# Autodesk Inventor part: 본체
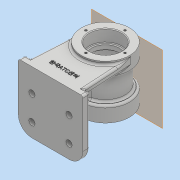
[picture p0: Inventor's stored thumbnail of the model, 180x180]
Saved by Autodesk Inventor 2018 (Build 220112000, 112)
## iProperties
Created: 2024-02
Part Number: 본체
Material: 일반
Document SubType Name: Modeling
Designer: home
Density: 1 g/cm^3
Appearance: 기본값
Author: home
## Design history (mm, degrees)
sketch "스케치2"
  geometry: L1 (-47, 45)-(47, 45); L2 (47, 45)-(47, -25); L3 (27, -45)-(-27, -45); L4 (-47, -25)-(-47, 45); L5 (-47, 45)-(47, -45); L6 (47, 45)-(-47, -45); A1 r 20 centre (27, -25) between (27, -45) and (47, -25); A2 r 20 centre (-27, -25) between (-47, -25) and (-27, -45); 1 further point
  constraints: 12 end point, 4 point on circle, 4 point on line, 4 tangent, 2 centre point, 2 midpoint, 2 parallel, 1 equal radius, 1 horizontal, 1 perpendicular
  dimensions: "d0" = 90 distance of L6.end L1.start; "d1" = 94 distance of L1.start L1.end; "d2" = 20 radius of A1
extrude "돌출1" new body sketch "스케치2" distance "d3" = 10; taper "d4" = 0 deg
sketch "스케치3"
  geometry: L1 (0, 0)-(70, 0); L2 (70, 0)-(70, 50); L3 (0, -45)-(-10, -45) reference; L4 (105, 50)-(94.5, 50); L5 (92.5, 32)-(90, 32); L6 (105, -28)-(94.5, -28); L7 (92.5, -10)-(90, -10); L8 (90.5, -4)-(90, -4); L9 (90.5, 26)-(90, 26); L10 (93.5, 49)-(93.5, 33); L11 (90, 32)-(90, 26); L12 (90, -4)-(90, -10); L13 (93.5, 23)-(93.5, -1); L14 (93.5, -11)-(93.5, -27); L15 (102, 28)-(98.5, 28); L16 (98.5, 28)-(98.5, -6); L17 (102, -6)-(98.5, -6); L18 (105, 50)-(105, 31); L19 (105, -9)-(105, -28); L20 (94.5, -28)-(93.5, -27); L21 (93.5, 49)-(94.5, 50); A1 r 3 centre (102, 31) between (102, 28) and (105, 31); A2 r 3 centre (102, -9) between (105, -9) and (102, -6); A3 r 1 centre (92.5, 33) between (92.5, 32) and (93.5, 33); A4 r 1 centre (92.5, -11) between (93.5, -11) and (92.5, -10); A5 r 3 centre (90.5, 23) between (93.5, 23) and (90.5, 26); A6 r 3 centre (90.5, -1) between (90.5, -4) and (93.5, -1); 4 further points
  constraints: 40 end point, 15 tangent, 12 point on circle, 10 perpendicular, 8 vertical, 6 centre point, 5 horizontal alignment, 4 horizontal, 4 point on line, 3 equal radius
  dimensions: "d5" = 70 distance of L1.start L1.end; "d9" = 95 distance from line of L2.end L3; "d10" = 18 distance between parallel lines of L5 L4; "d11" = 78 distance from line of L6.start L4; "d12" = 18 distance between parallel lines of L7 L6; "d13" = 6 distance between parallel lines of L9 L5; "d14" = 6 distance between parallel lines of L8 L7; "d15" = 22 distance between parallel lines of L15 L4; "d16" = 57 diameter of L16 L2; "d17" = 22 distance between parallel lines of L17 L6; "d18" = 3 radius of A1; "d19" = 1 radius of A3; "d20" = 3 radius of A5; "d21" = 1 distance of L6.end point (93.5, -28); "d22" = 1 distance of L14.end point (93.5, -28) (= d21); "d23" = 1 distance of L10.start point (93.5, 50) (= d21); "d24" = 1 distance of L4.end point (93.5, 50) (= d23); "d27" = 5 distance between parallel lines of L13 L16; "d31" = 15 distance from line of point (90, -28) L18; "d32" = 70 diameter of L18 L2; "d33" = 15 distance between parallel lines of L11 L18; "d34" = 15 distance between parallel lines of L12 L18; "d35" = 15 distance from line of point (90, 50) L18
revolve "회전1" sketch "스케치3" stored, may be unused: angle "d36" = 90 deg
sketch "스케치4"
  geometry: L1 (47, -45)-(-47, -45) reference; L2 (47, -45)-(47, -11); L3 (47, 25)-(47, -45) reference; L4 (47, -11)-(27, -11); L5 (47, -11)-(47, 25); L6 (47, 25)-(27, 25); C1 r 10 at (27, 25); C2 r 10 at (27, -11); 1 further point
  constraints: 8 end point, 2 centre point, 2 coincident, 2 horizontal, 2 point on line
  dimensions: "d37" = 34 distance of L1.start L2.end; "d38" = 20 distance of L2.end L4.end; "d39" = 36 distance of L5.end L2.end; "d40" = 20 distance of L5.end L6.end; "d41" = 20 diameter of C1; "d42" = 20 diameter of C2
extrude "돌출2" join sketch "스케치4" distance "d43" = 3; taper "d44" = 0 deg
fillet "모깎기1" dims "d45" = 3
sketch "스케치5"
  geometry: C1 r 10 at (0, 0) reference; C2 r 13 at (0, 0) reference; C3 r 13 at (0, -36) reference; C4 r 13 at (-54, 0) reference; C5 r 13 at (-54, -36) reference; 5 further points
  constraints: 4 coincident
hole "구멍1" sketch "스케치5" at (-54, 0), (0, 0), (0, -36), (-54, -36) diameter "d46" = 9; stored, may be unused: countersink angle "d50" = 90 deg, drill point angle "d52" = 118 deg; dims "d47" = 6, "d48" = 4, "d49" = 2, "d51" = 8
sketch "스케치6"
  geometry: L1 (0, -10)-(8, -10); L2 (0, -10)-(20, -10) reference; L3 (94, -10)-(0, -10) reference; L4 (94, -10)-(86, -10); L5 (8, -10)-(8, 0); L6 (8, 0)-(12.055, 71.969); L7 (86, -10)-(86, 0); L8 (94, 0)-(0, 0) reference; L9 (86, 0)-(81.945, 71.969); L10 (12.055, 71.969)-(26.283, 43.904); L11 (26.283, 43.904)-(48.752, 37.119); L12 (48.752, 37.119)-(69.663, 45.239); L13 (69.663, 45.239)-(77.598, 56.815); L14 (77.598, 56.815)-(81.945, 71.969); L15 (8, -10)-(86, -10); A1 r 35 centre (47, 70) between (12.055, 71.969) and (81.945, 71.969) reference; 1 further point
  constraints: 24 end point, 3 point on line, 2 point on circle, 2 tangent, 2 vertical, 1 horizontal
  dimensions: "d53" = 8 distance of L1.start L1.end; "d54" = 8 distance of L4.end L3.start; "d55" = 86.7748 deg angle of L8 L6; "d56" = 106.006 deg angle of L3 L14; "d57" = 55.5722 deg angle of L3 L13; "d58" = 21.2211 deg angle of L3 L12; "d59" = 16.8033 deg angle of L3 L11; "d60" = 63.1166 deg angle of L3 L10; "d61" = 45.65079 distance from line of L8.start L13; "d62" = 50.98071 distance from line of L8.start L12; "d63" = 22.45383 distance from line of L8.start L11
extrude "돌출3" join sketch "스케치6" distance "d64" = 10; taper "d65" = 0 deg
sketch "스케치8"
  geometry: L1 (0, -45)-(-10, -45) reference; L2 (0, -45)-(0, -33); L3 (0, -25)-(0, -45) reference; L4 (0, -33)-(42.502, -17.531); L5 (42.502, -17.531)-(42.502, 36.947); L6 (41.5, 28)-(41.5, -6) reference; L7 (42.502, 36.947)-(0, 36.947); L8 (0, 36.947)-(0, -33); 1 further point
  constraints: 10 end point, 2 perpendicular, 1 parallel, 1 point on line
  dimensions: "d66" = 12 distance of L1.start L2.end; "d67" = 70 deg angle of L8 L4; "d68" = 42.50207 distance between parallel lines of L8 L5; "d69" = 69.94666 distance from line of L2.end L7
extrude "돌출4" join sketch "스케치8" stored distance "d70" = 10; taper "d71" = 0 deg
fillet "모깎기3" dims "d73" = 3
fillet "모깎기4" dims "d74" = 3
fillet "모깎기5" dims "d75" = 3
fillet "모깎기6" dims "d76" = 3
fillet "모깎기9" dims "d79" = 3
fillet "모깎기10" dims "d80" = 3
fillet "모깎기11" dims "d81" = 3
fillet "모깎기12" dims "d82" = 3
fillet "모깎기13" dims "d83" = 3
fillet "모깎기14" dims "d84" = 3
sketch "스케치9"
  geometry: L1 (0, 0)-(0, 28.5); C1 r 35 at (0, 0) reference; A1 r 28.5 centre (0, 0) between (-7.238, -27.566) and (7.238, -27.566); A2 r 28.5 centre (0, 0) between (7.238, -27.566) and (-7.238, -27.566) reference; 2 further points
  constraints: 2 coincident, 2 end point, 1 centre point, 1 point on circle, 1 vertical
  dimensions: "d85" = 57 diameter of A1
hole "구멍2" sketch "스케치9" at (0, 28.5) diameter "d86" = 3.242; stored, may be unused: countersink angle "d90" = 90 deg, drill point angle "d92" = 118 deg; dims "d87" = 8, "d88" = 4, "d89" = 2, "d91" = 10
sketch "스케치10" dims "d96" = 57
  geometry: L1 (0, 0)-(0, 28.5); C1 r 35 at (0, 0) reference; 2 further points
  constraints: 2 coincident, 2 end point, 1 vertical, 1 vertical alignment, 2 other
hole "구멍3" sketch "스케치10" at (0, 28.5) diameter "d97" = 3.242; stored, may be unused: countersink angle "d101" = 90 deg, drill point angle "d103" = 118 deg; dims "d98" = 8, "d99" = 4, "d100" = 2, "d102" = 10
sketch "스케치11"
  geometry: L1 (88, 0)-(0, 0) reference; L2 (91, 0)-(91, 7) reference; 2 further points
  constraints: 1 other
  dimensions: "d107" = 20 distance from line of point (44, 20) L1; "d108" = 47 distance from line of point (44, 20) L2
feature "엠보싱1" sketch "스케치11" dims "d0" = 90, "d1" = 94, "d2" = 20, "d5" = 70, "d9" = 95, "d10" = 18, "d11" = 78, "d12" = 18, "d13" = 6, "d14" = 6, "d15" = 22, "d16" = 57, "d17" = 22, "d18" = 3, "d19" = 1, "d20" = 3, "d21" = 1, "d22" = 1 (= d21), "d23" = 1 (= d21), "d24" = 1 (= d23), "d27" = 5, "d31" = 15, "d32" = 70, "d33" = 15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
node "작업 평면1"
sketch "스케치12"
  geometry: L1 (-31.5, 28)-(31.5, 28) reference; L2 (-24.5, 50)-(24.5, 50) reference; L3 (0, 50)-(0, 11); C1 r 6 at (0, 11); 3 further points
  constraints: 2 end point, 1 centre point, 1 coincident, 1 midpoint, 1 vertical
  dimensions: "d112" = 39 distance of L3.start L3.end; "d113" = 12 diameter of C1
extrude "돌출5" join sketch "스케치12" stored distance "d114" = 10; taper "d115" = 0 deg
sketch "스케치13"
  geometry: C1 r 6 at (0, 0) reference; C2 r 3.5 at (0, 0); 2 further points
  constraints: 2 coincident, 1 centre point
  dimensions: "d116" = 7 diameter of C2
extrude "돌출6" cut sketch "스케치13" distance "d117" = 2; taper "d118" = 0 deg
sketch "스케치14"
  geometry: C1 r 3.5 at (0, 0) reference; C2 r 6 at (0, 0) reference; 2 further points
  constraints: 1 coincident
hole "구멍4" sketch "스케치14" at (0, 0) diameter "d119" = 5.188; stored, may be unused: countersink angle "d123" = 90 deg, drill point angle "d125" = 118 deg; dims "d120" = 12, "d121" = 4, "d122" = 2, "d124" = 16
fillet "모깎기15" dims "d126" = 3
node "솔리드1"
mirror "미러1"
pattern_circular "원형 패턴1" dims angle "d94" = 360 deg
pattern_circular "원형 패턴2" dims angle "d105" = 360 deg
node "투영된 루프1"
node "투영된 루프2"
other parameters: "d7" = 47, "d111" = -111.5
